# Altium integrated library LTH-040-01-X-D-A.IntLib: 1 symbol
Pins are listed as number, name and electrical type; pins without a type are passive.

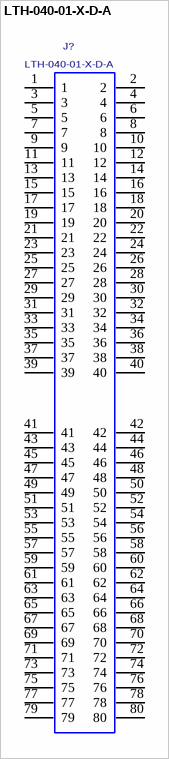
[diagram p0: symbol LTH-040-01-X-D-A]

## LTH-040-01-X-D-A
designator J?
0.50mm DOUBLE ROW LOW PROFILE TERMINAL ASSEMBLY; MANUFACTURER: SAMTEC
footprint LTH-040-01-X-D-A
pins: 1, 2, 3, 4, 5, 6, 7, 8, 9, 10, 11, 12, 13, 14, 15, 16, 17, 18, 19, 20, 21, 22, 23, 24, 25, 26, 27, 28, 29, 30, 31, 32, 33, 34, 35, 36, 37, 38, 39, 40, 41, 42, 43, 44, 45, 46, 47, 48, 49, 50, 51, 52, 53, 54, 55, 56, 57, 58, 59, 60, 61, 62, 63, 64, 65, 66, 67, 68, 69, 70, 71, 72, 73, 74, 75, 76, 77, 78, 79, 80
